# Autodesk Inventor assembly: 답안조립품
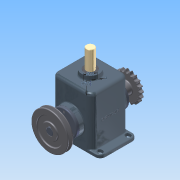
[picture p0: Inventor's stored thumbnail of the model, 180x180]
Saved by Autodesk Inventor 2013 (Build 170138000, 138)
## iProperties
Created: 2015-03
Part Number: 답안조립품
Document SubType Name: Assembly
Designer: User11
Author: User11
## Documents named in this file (15)
- C:\Users\User11\Desktop\350305V1009\답안조립품.iam
- C:\Users\User11\Desktop\350305V1009\본체.ipt
- C:\Users\User11\Desktop\350305V1009\편심축.ipt
- C:\Users\User11\Desktop\350305V1009\V-벨트풀리.ipt
- C:\Users\User11\Desktop\350305V1009\체인 스프로킷.ipt
- C:\Users\User11\Desktop\350305V1009\커버.ipt
- C:\Users\User11\Desktop\350305V1009\슬라이드.ipt
- C:\Users\User11\Desktop\350305V1009\가변스프링.ipt
- C:\Users\User11\Desktop\350305V1009\베어링 6205.ipt
- C:\Users\User11\Desktop\350305V1009\오일실.ipt
- C:\Users\User11\Desktop\350305V1009\부시.ipt
- C:\Users\User11\Desktop\350305V1009\키 8x8.ipt
- C:\Users\User11\Desktop\350305V1009\멈춤링.ipt
- C:\Users\User11\Desktop\350305V1009\M4x0.5.ipt
- C:\Users\User11\Desktop\350305V1009\멈춤나사 M5x0.5.ipt
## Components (9 placed, 4 different names)
1. V-벨트풀리:1 — 각도:3, 플러쉬:5
2. 5-체인 스프로킷:1 — 각도:4, 플러쉬:6
3. 가변스프링:1
4. M4x0.5:1 — 플러쉬:1, 각도:5
5. M4x0.5:2 — 플러쉬:1, 플러쉬:2, 각도:6, 각도:7
6. M4x0.5:3 — 플러쉬:2, 각도:5, 각도:6
7. M4x0.5:4 — 플러쉬:3, 각도:8
8. M4x0.5:5 — 플러쉬:3, 플러쉬:4, 각도:8, 각도:9, 각도:10
9. M4x0.5:6 — 플러쉬:4, 각도:9
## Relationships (14: Angle 8, Flush 6)
- 각도:3 [Angle]: V-벨트풀리:1
- 각도:4 [Angle]: 5-체인 스프로킷:1
- 플러쉬:1 [Flush]: M4x0.5:1 ↔ M4x0.5:2
- 플러쉬:2 [Flush]: M4x0.5:2 ↔ M4x0.5:3
- 각도:5 [Angle]: M4x0.5:1 ↔ M4x0.5:3
- 각도:6 [Angle]: M4x0.5:2 ↔ M4x0.5:3
- 각도:7 [Angle]: M4x0.5:2
- 플러쉬:3 [Flush]: M4x0.5:4 ↔ M4x0.5:5
- 플러쉬:4 [Flush]: M4x0.5:5 ↔ M4x0.5:6
- 각도:8 [Angle]: M4x0.5:4 ↔ M4x0.5:5
- 각도:9 [Angle]: M4x0.5:5 ↔ M4x0.5:6
- 각도:10 [Angle]: M4x0.5:5
- 플러쉬:5 [Flush]: V-벨트풀리:1
- 플러쉬:6 [Flush]: 5-체인 스프로킷:1
